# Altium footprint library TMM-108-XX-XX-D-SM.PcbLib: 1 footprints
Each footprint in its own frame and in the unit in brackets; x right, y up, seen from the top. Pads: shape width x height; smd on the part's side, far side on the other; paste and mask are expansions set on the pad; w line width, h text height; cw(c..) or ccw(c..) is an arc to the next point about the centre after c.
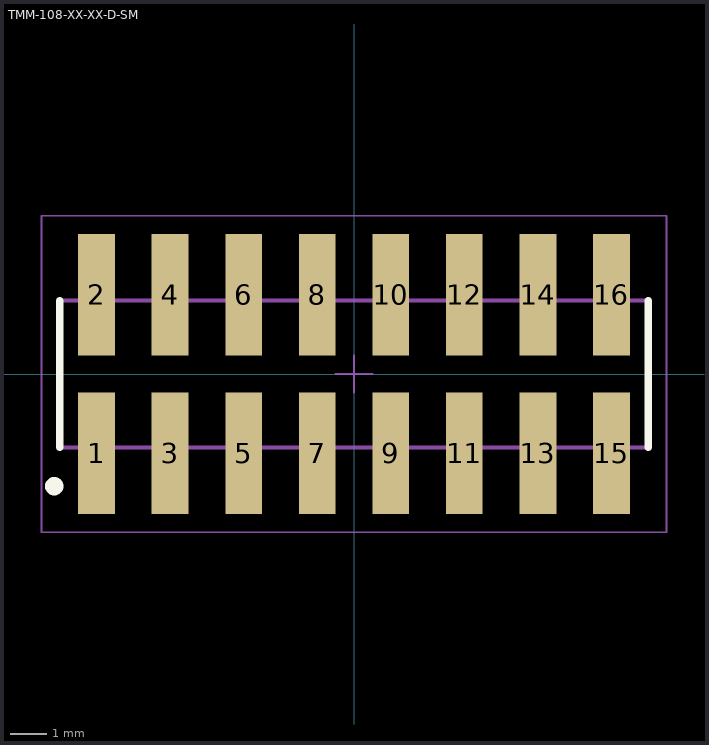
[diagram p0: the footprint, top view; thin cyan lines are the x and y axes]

## TMM-108-XX-XX-D-SM [mm] "2.00mm pitch, 16 pin, terminal strip; double row, SMT"
height 2.77
pads (16):
  rect 1x3.3 smd mask+0: 1(-7,-2.15) 2(-7,2.15) 3(-5,-2.15) 4(-5,2.15) 5(-3,-2.15) 6(-3,2.15) 7(-1,-2.15) 8(-1,2.15) 9(1,-2.15) 10(1,2.15) 11(3,-2.15) 12(3,2.15) 13(5,-2.15) 14(5,2.15) 15(7,-2.15) 16(7,2.15)
Top Overlay:
  circle w0.25: c-8.15,-3.05 r0.125
  lines w0.2: -8,-2 -8,2 ; 8,-2 8,2
Mechanical 12:
  lines w0.001: -8,-2 8,-2 8,2 -8,2 -8,-2
Mechanical 13:
  lines w0.1: -8,-2 8,-2 8,2 -8,2 -8,-2
  text ".Designator" at 0,-0.127 h1.52
Mechanical 15:
  lines w0.05: -0.5,0 0.5,0 ; 0,-0.5 0,0.5 ; -8.5,-4.3 8.5,-4.3 8.5,4.3 -8.5,4.3 -8.5,-4.3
